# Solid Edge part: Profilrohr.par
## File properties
Username: ahadarics
Dokumentum tartalom típus: 0
Author: ahadarics
Last saved by: ahadarics
Revision: 87
Sűrűség: 0,000 kg/m^3
Pontosság: 0,990
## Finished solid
Body 1: solid body, 6 faces, 6 edges, 0 vertices.
  Faces by surface: cone 2, cylinder 2, plane 2
  Edges by curve: circle 6
Bounding box of the edges (mm): 26.500 x 26.500 x 533.000, from (-13.25, -13.25, -511.5) to (13.25, 13.25, 21.5).
Cylindrical faces by radius (mm): R12.5 x1, R13.25 x1
Conical faces (half-angle, radius in mm at the cone's reference point): 15 deg R12.567 x2
Planar faces by outward normal: +z 1, -z 1
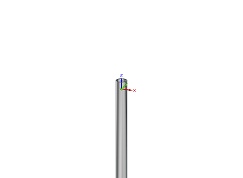
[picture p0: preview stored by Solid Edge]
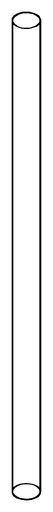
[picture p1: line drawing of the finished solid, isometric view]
